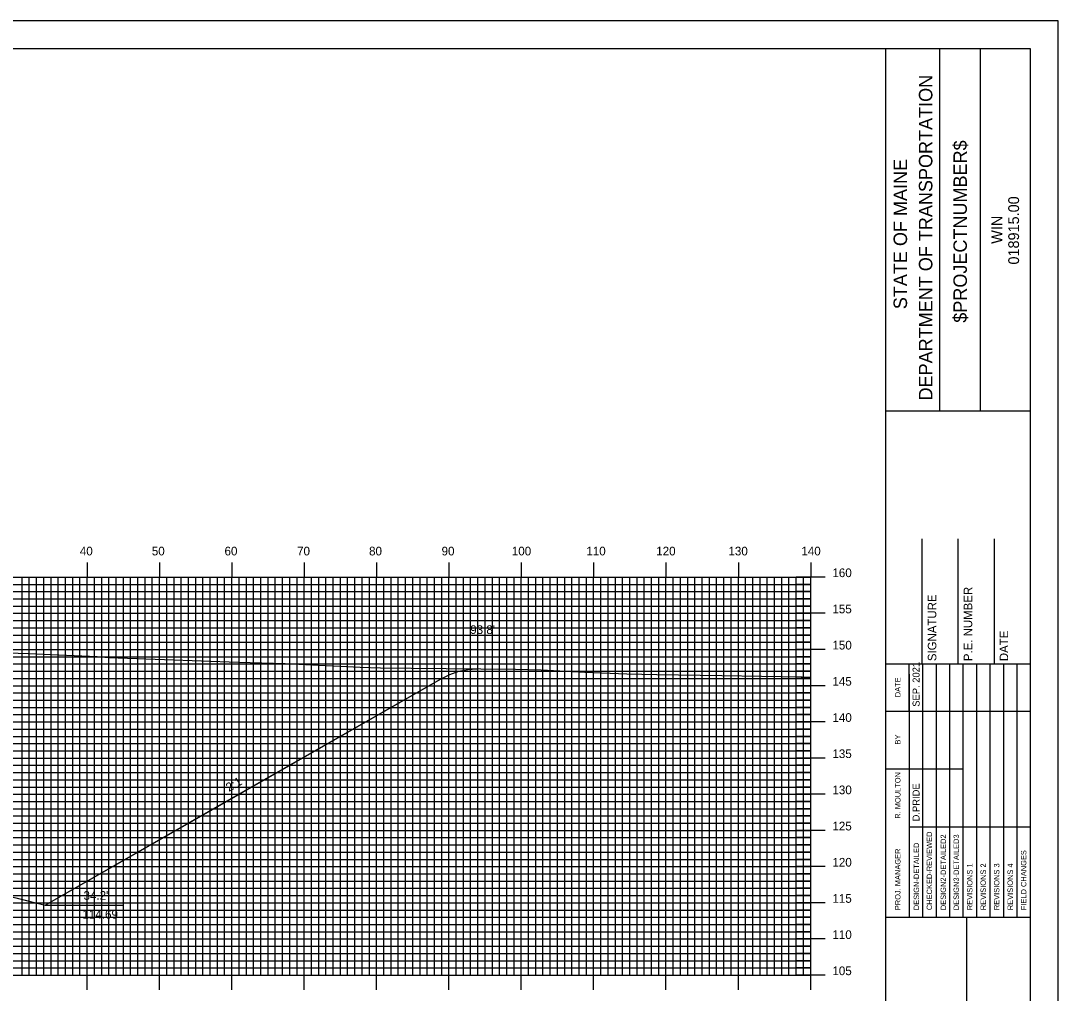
# Model space of a CAD drawing. Extents: x 1769661 to 1770005, y 442591 to 442811.
# Drawn here: x 1769857.8 to 1770001.2, y 442676.2 to 442810.5 of the extents above; entities that cross this region are included whole.
import ezdxf

# ---------------------------------------------------------------- set-up
doc = ezdxf.new("R2010")
doc.units = 0
for name, color, linetype in [('ANNOTATION', 7, 'Continuous'), ('BORDER', 7, 'Continuous'), ('D_Roadway_Centerline', 7, 'Continuous'), ('D_Roadway_SlopeLines', 7, 'Continuous'), ('D_Text_Standard', 7, 'Continuous'), ('H_V ANNOTATION', 7, 'Continuous'), ('MAJOR', 7, 'Continuous'), ('MINOR', 7, 'Continuous'), ('PDRAIN', 7, 'Continuous'), ('PLOT BOUNDARY', 7, 'Continuous'), ('S_Roadway_Centerline', 7, 'Continuous')]:
    doc.layers.add(name, color=color, linetype=linetype)

msp = doc.modelspace()

# ---------------------------------------------------------------- linework, layer by layer
at = {"layer": 'BORDER'}
for p, q in [((1769977.41, 442596.67), (1769977.41, 442806.67)), ((1769984.87, 442756.66), (1769984.87, 442806.66)), ((1769990.46, 442756.66), (1769990.46, 442806.66)), ((1769977.42, 442756.65), (1769997.41, 442756.65)), ((1769982.41, 442721.67), (1769982.41, 442738.97)), ((1769987.41, 442721.67), (1769987.41, 442738.97)), ((1769992.41, 442721.67), (1769992.41, 442738.97)), ((1769977.41, 442721.67), (1769997.41, 442721.67)), ((1769977.41, 442686.67), (1769997.41, 442686.67)), ((1769988.6, 442616.67), (1769988.6, 442686.67))]:
    msp.add_line(p, q, dxfattribs=at)
msp.add_lwpolyline([(1769677.41, 442596.67), (1769997.41, 442596.67), (1769997.41, 442806.67), (1769677.41, 442806.67)], close=True, dxfattribs=at)
for points in [[(1769980.64, 442715.17), (1769980.64, 442721.67)], [(1769982.51, 442686.68), (1769982.51, 442721.67)], [(1769984.37, 442721.67), (1769984.37, 442686.68)], [(1769986.24, 442686.68), (1769986.24, 442721.67)], [(1769988.1, 442686.68), (1769988.1, 442721.67)], [(1769989.96, 442686.68), (1769989.96, 442721.67)], [(1769991.83, 442686.68), (1769991.83, 442721.67)], [(1769993.69, 442686.68), (1769993.69, 442721.67)], [(1769995.55, 442686.68), (1769995.55, 442721.67)], [(1769980.65, 442686.68), (1769980.65, 442720.26)], [(1769977.41, 442715.17), (1769997.41, 442715.17)], [(1769977.41, 442707.17), (1769980.65, 442707.17)], [(1769980.64, 442707.17), (1769988.1, 442707.17)], [(1769980.64, 442699.17), (1769997.41, 442699.17)]]:
    msp.add_lwpolyline(points, dxfattribs=at)
at = {"layer": 'D_Roadway_Centerline'}
msp.add_lwpolyline([(1769857.19, 442689.35), (1769861.19, 442688.35), (1769861.19, 442688.36), (1769886.93, 442703.06), (1769915.86, 442719.59), (1769916.66, 442719.99), (1769917.11, 442720.22), (1769918.36, 442720.66), (1769919.15, 442720.82), (1769919.61, 442720.92), (1769920.05, 442720.94), (1769920.86, 442720.99)], dxfattribs=at)
at = {"layer": 'D_Roadway_SlopeLines'}
for points in [[(1769861.19, 442688.35), (1769915.86, 442719.59), (1769917.11, 442720.22), (1769918.36, 442720.66), (1769919.61, 442720.92), (1769920.86, 442720.99)], [(1769847.02, 442691.9), (1769861.19, 442688.35)]]:
    msp.add_lwpolyline(points, dxfattribs=at)
at = {"layer": 'MAJOR'}
for p, q in [((1769867.01, 442735.67), (1769867.01, 442733.67)), ((1769877.01, 442735.67), (1769877.01, 442733.67)), ((1769887.01, 442735.67), (1769887.01, 442733.67)), ((1769897.01, 442735.67), (1769897.01, 442733.67)), ((1769907.01, 442735.67), (1769907.01, 442733.67)), ((1769917.01, 442735.67), (1769917.01, 442733.67)), ((1769927.01, 442735.67), (1769927.01, 442733.67)), ((1769937.01, 442735.67), (1769937.01, 442733.67)), ((1769947.01, 442735.67), (1769947.01, 442733.67)), ((1769957.01, 442735.67), (1769957.01, 442733.67)), ((1769967.01, 442735.67), (1769967.01, 442733.67)), ((1769687.01, 442733.67), (1769967.01, 442733.67)), ((1769687.01, 442733.67), (1769967.01, 442733.67)), ((1769867.01, 442678.67), (1769867.01, 442733.67)), ((1769877.01, 442678.67), (1769877.01, 442733.67)), ((1769887.01, 442678.67), (1769887.01, 442733.67)), ((1769897.01, 442678.67), (1769897.01, 442733.67)), ((1769907.01, 442678.67), (1769907.01, 442733.67)), ((1769917.01, 442678.67), (1769917.01, 442733.67)), ((1769927.01, 442678.67), (1769927.01, 442733.67)), ((1769937.01, 442678.67), (1769937.01, 442733.67)), ((1769947.01, 442678.67), (1769947.01, 442733.67)), ((1769957.01, 442678.67), (1769957.01, 442733.67)), ((1769969.02, 442733.67), (1769965.01, 442733.67)), ((1769967.01, 442678.67), (1769967.01, 442733.67)), ((1769967.01, 442678.67), (1769967.01, 442733.67)), ((1769687.01, 442728.67), (1769967.01, 442728.67)), ((1769969.02, 442728.67), (1769965.01, 442728.67)), ((1769687.01, 442723.67), (1769967.01, 442723.67)), ((1769969.02, 442723.67), (1769965.01, 442723.67)), ((1769687.01, 442718.67), (1769967.01, 442718.67)), ((1769969.02, 442718.67), (1769965.01, 442718.67)), ((1769687.01, 442713.67), (1769967.01, 442713.67)), ((1769969.02, 442713.67), (1769965.01, 442713.67)), ((1769687.01, 442708.67), (1769967.01, 442708.67)), ((1769969.02, 442708.67), (1769965.01, 442708.67)), ((1769687.01, 442703.67), (1769967.01, 442703.67)), ((1769969.02, 442703.67), (1769965.01, 442703.67)), ((1769687.01, 442698.67), (1769967.01, 442698.67)), ((1769969.02, 442698.67), (1769965.01, 442698.67)), ((1769687.01, 442693.67), (1769967.01, 442693.67)), ((1769969.02, 442693.67), (1769965.01, 442693.67)), ((1769687.01, 442688.67), (1769967.01, 442688.67)), ((1769969.02, 442688.67), (1769965.01, 442688.67)), ((1769687.01, 442683.67), (1769967.01, 442683.67)), ((1769969.02, 442683.67), (1769965.01, 442683.67)), ((1769687.01, 442678.67), (1769967.01, 442678.67)), ((1769687.01, 442678.67), (1769967.01, 442678.67)), ((1769867.01, 442676.66), (1769867.01, 442678.67)), ((1769877.01, 442676.66), (1769877.01, 442678.67)), ((1769887.01, 442676.66), (1769887.01, 442678.67)), ((1769897.01, 442676.66), (1769897.01, 442678.67)), ((1769907.01, 442676.66), (1769907.01, 442678.67)), ((1769917.01, 442676.66), (1769917.01, 442678.67)), ((1769927.01, 442676.66), (1769927.01, 442678.67)), ((1769937.01, 442676.66), (1769937.01, 442678.67)), ((1769947.01, 442676.66), (1769947.01, 442678.67)), ((1769957.01, 442676.66), (1769957.01, 442678.67)), ((1769969.02, 442678.67), (1769965.01, 442678.67)), ((1769967.01, 442676.66), (1769967.01, 442678.67))]:
    msp.add_line(p, q, dxfattribs=at)
at = {"layer": 'MINOR'}
for p, q in [((1769687.01, 442732.67), (1769967.01, 442732.67)), ((1769858.01, 442678.67), (1769858.01, 442733.67)), ((1769859.01, 442678.67), (1769859.01, 442733.67)), ((1769860.01, 442678.67), (1769860.01, 442733.67)), ((1769861.01, 442678.67), (1769861.01, 442733.67)), ((1769862.01, 442678.67), (1769862.01, 442733.67)), ((1769863.01, 442678.67), (1769863.01, 442733.67)), ((1769864.01, 442678.67), (1769864.01, 442733.67)), ((1769865.01, 442678.67), (1769865.01, 442733.67)), ((1769866.01, 442678.67), (1769866.01, 442733.67)), ((1769868.01, 442678.67), (1769868.01, 442733.67)), ((1769869.01, 442678.67), (1769869.01, 442733.67)), ((1769870.01, 442678.67), (1769870.01, 442733.67)), ((1769871.01, 442678.67), (1769871.01, 442733.67)), ((1769872.01, 442678.67), (1769872.01, 442733.67)), ((1769873.01, 442678.67), (1769873.01, 442733.67)), ((1769874.01, 442678.67), (1769874.01, 442733.67)), ((1769875.01, 442678.67), (1769875.01, 442733.67)), ((1769876.01, 442678.67), (1769876.01, 442733.67)), ((1769878.01, 442678.67), (1769878.01, 442733.67)), ((1769879.01, 442678.67), (1769879.01, 442733.67)), ((1769880.01, 442678.67), (1769880.01, 442733.67)), ((1769881.01, 442678.67), (1769881.01, 442733.67)), ((1769882.01, 442678.67), (1769882.01, 442733.67)), ((1769883.01, 442678.67), (1769883.01, 442733.67)), ((1769884.01, 442678.67), (1769884.01, 442733.67)), ((1769885.01, 442678.67), (1769885.01, 442733.67)), ((1769886.01, 442678.67), (1769886.01, 442733.67)), ((1769888.01, 442678.67), (1769888.01, 442733.67)), ((1769889.01, 442678.67), (1769889.01, 442733.67)), ((1769890.01, 442678.67), (1769890.01, 442733.67)), ((1769891.01, 442678.67), (1769891.01, 442733.67)), ((1769892.01, 442678.67), (1769892.01, 442733.67)), ((1769893.01, 442678.67), (1769893.01, 442733.67)), ((1769894.01, 442678.67), (1769894.01, 442733.67)), ((1769895.01, 442678.67), (1769895.01, 442733.67)), ((1769896.01, 442678.67), (1769896.01, 442733.67)), ((1769898.01, 442678.67), (1769898.01, 442733.67)), ((1769899.01, 442678.67), (1769899.01, 442733.67)), ((1769900.01, 442678.67), (1769900.01, 442733.67)), ((1769901.01, 442678.67), (1769901.01, 442733.67)), ((1769902.01, 442678.67), (1769902.01, 442733.67)), ((1769903.01, 442678.67), (1769903.01, 442733.67)), ((1769904.01, 442678.67), (1769904.01, 442733.67)), ((1769905.01, 442678.67), (1769905.01, 442733.67)), ((1769906.01, 442678.67), (1769906.01, 442733.67)), ((1769908.01, 442678.67), (1769908.01, 442733.67)), ((1769909.01, 442678.67), (1769909.01, 442733.67)), ((1769910.01, 442678.67), (1769910.01, 442733.67)), ((1769911.01, 442678.67), (1769911.01, 442733.67)), ((1769912.01, 442678.67), (1769912.01, 442733.67)), ((1769913.01, 442678.67), (1769913.01, 442733.67)), ((1769914.01, 442678.67), (1769914.01, 442733.67)), ((1769915.01, 442678.67), (1769915.01, 442733.67)), ((1769916.01, 442678.67), (1769916.01, 442733.67)), ((1769918.01, 442678.67), (1769918.01, 442733.67)), ((1769919.01, 442678.67), (1769919.01, 442733.67)), ((1769920.01, 442678.67), (1769920.01, 442733.67)), ((1769921.01, 442678.67), (1769921.01, 442733.67)), ((1769922.01, 442678.67), (1769922.01, 442733.67)), ((1769923.01, 442678.67), (1769923.01, 442733.67)), ((1769924.01, 442678.67), (1769924.01, 442733.67)), ((1769925.01, 442678.67), (1769925.01, 442733.67)), ((1769926.01, 442678.67), (1769926.01, 442733.67)), ((1769928.01, 442678.67), (1769928.01, 442733.67)), ((1769929.01, 442678.67), (1769929.01, 442733.67)), ((1769930.01, 442678.67), (1769930.01, 442733.67)), ((1769931.01, 442678.67), (1769931.01, 442733.67)), ((1769932.01, 442678.67), (1769932.01, 442733.67)), ((1769933.01, 442678.67), (1769933.01, 442733.67)), ((1769934.01, 442678.67), (1769934.01, 442733.67)), ((1769935.01, 442678.67), (1769935.01, 442733.67)), ((1769936.01, 442678.67), (1769936.01, 442733.67)), ((1769938.01, 442678.67), (1769938.01, 442733.67)), ((1769939.01, 442678.67), (1769939.01, 442733.67)), ((1769940.01, 442678.67), (1769940.01, 442733.67)), ((1769941.01, 442678.67), (1769941.01, 442733.67)), ((1769942.01, 442678.67), (1769942.01, 442733.67)), ((1769943.01, 442678.67), (1769943.01, 442733.67)), ((1769944.01, 442678.67), (1769944.01, 442733.67)), ((1769945.01, 442678.67), (1769945.01, 442733.67)), ((1769946.01, 442678.67), (1769946.01, 442733.67)), ((1769948.01, 442678.67), (1769948.01, 442733.67)), ((1769949.01, 442678.67), (1769949.01, 442733.67)), ((1769950.01, 442678.67), (1769950.01, 442733.67)), ((1769951.01, 442678.67), (1769951.01, 442733.67)), ((1769952.01, 442678.67), (1769952.01, 442733.67)), ((1769953.01, 442678.67), (1769953.01, 442733.67)), ((1769954.01, 442678.67), (1769954.01, 442733.67)), ((1769955.01, 442678.67), (1769955.01, 442733.67)), ((1769956.01, 442678.67), (1769956.01, 442733.67)), ((1769958.01, 442678.67), (1769958.01, 442733.67)), ((1769959.01, 442678.67), (1769959.01, 442733.67)), ((1769960.01, 442678.67), (1769960.01, 442733.67)), ((1769961.01, 442678.67), (1769961.01, 442733.67)), ((1769962.01, 442678.67), (1769962.01, 442733.67)), ((1769963.01, 442678.67), (1769963.01, 442733.67)), ((1769964.01, 442678.67), (1769964.01, 442733.67)), ((1769965.01, 442678.67), (1769965.01, 442733.67)), ((1769967.01, 442732.67), (1769965.01, 442732.67)), ((1769966.01, 442678.67), (1769966.01, 442733.67)), ((1769687.01, 442731.67), (1769967.01, 442731.67)), ((1769967.01, 442731.67), (1769965.01, 442731.67)), ((1769687.01, 442730.67), (1769967.01, 442730.67)), ((1769967.01, 442730.67), (1769965.01, 442730.67)), ((1769687.01, 442729.67), (1769967.01, 442729.67)), ((1769967.01, 442729.67), (1769965.01, 442729.67)), ((1769687.01, 442727.67), (1769967.01, 442727.67)), ((1769967.01, 442727.67), (1769965.01, 442727.67)), ((1769687.01, 442726.67), (1769967.01, 442726.67)), ((1769687.01, 442725.67), (1769967.01, 442725.67)), ((1769967.01, 442726.67), (1769965.01, 442726.67)), ((1769967.01, 442725.67), (1769965.01, 442725.67)), ((1769687.01, 442724.67), (1769967.01, 442724.67)), ((1769967.01, 442724.67), (1769965.01, 442724.67)), ((1769687.01, 442722.67), (1769967.01, 442722.67)), ((1769967.01, 442722.67), (1769965.01, 442722.67)), ((1769687.01, 442721.67), (1769967.01, 442721.67)), ((1769967.01, 442721.67), (1769965.01, 442721.67)), ((1769687.01, 442720.67), (1769967.01, 442720.67)), ((1769687.01, 442719.67), (1769967.01, 442719.67)), ((1769967.01, 442720.67), (1769965.01, 442720.67)), ((1769967.01, 442719.67), (1769965.01, 442719.67)), ((1769687.01, 442717.67), (1769967.01, 442717.67)), ((1769967.01, 442717.67), (1769965.01, 442717.67)), ((1769687.01, 442716.67), (1769967.01, 442716.67)), ((1769687.01, 442715.67), (1769967.01, 442715.67)), ((1769967.01, 442716.67), (1769965.01, 442716.67)), ((1769967.01, 442715.67), (1769965.01, 442715.67)), ((1769687.01, 442714.67), (1769967.01, 442714.67)), ((1769967.01, 442714.67), (1769965.01, 442714.67)), ((1769687.01, 442712.67), (1769967.01, 442712.67)), ((1769967.01, 442712.67), (1769965.01, 442712.67)), ((1769687.01, 442711.67), (1769967.01, 442711.67)), ((1769967.01, 442711.67), (1769965.01, 442711.67)), ((1769687.01, 442710.67), (1769967.01, 442710.67)), ((1769687.01, 442709.67), (1769967.01, 442709.67)), ((1769967.01, 442710.67), (1769965.01, 442710.67)), ((1769967.01, 442709.67), (1769965.01, 442709.67)), ((1769687.01, 442707.67), (1769967.01, 442707.67)), ((1769967.01, 442707.67), (1769965.01, 442707.67)), ((1769687.01, 442706.67), (1769967.01, 442706.67)), ((1769687.01, 442705.67), (1769967.01, 442705.67)), ((1769967.01, 442706.67), (1769965.01, 442706.67)), ((1769967.01, 442705.67), (1769965.01, 442705.67)), ((1769687.01, 442704.67), (1769967.01, 442704.67)), ((1769967.01, 442704.67), (1769965.01, 442704.67)), ((1769687.01, 442702.67), (1769967.01, 442702.67)), ((1769967.01, 442702.67), (1769965.01, 442702.67)), ((1769687.01, 442701.67), (1769967.01, 442701.67)), ((1769967.01, 442701.67), (1769965.01, 442701.67)), ((1769687.01, 442700.67), (1769967.01, 442700.67)), ((1769687.01, 442699.67), (1769967.01, 442699.67)), ((1769967.01, 442700.67), (1769965.01, 442700.67)), ((1769967.01, 442699.67), (1769965.01, 442699.67)), ((1769687.01, 442697.67), (1769967.01, 442697.67)), ((1769967.01, 442697.67), (1769965.01, 442697.67)), ((1769687.01, 442696.67), (1769967.01, 442696.67)), ((1769687.01, 442695.67), (1769967.01, 442695.67)), ((1769967.01, 442696.67), (1769965.01, 442696.67)), ((1769967.01, 442695.67), (1769965.01, 442695.67)), ((1769687.01, 442694.67), (1769967.01, 442694.67)), ((1769967.01, 442694.67), (1769965.01, 442694.67)), ((1769687.01, 442692.67), (1769967.01, 442692.67)), ((1769967.01, 442692.67), (1769965.01, 442692.67)), ((1769687.01, 442691.67), (1769967.01, 442691.67)), ((1769967.01, 442691.67), (1769965.01, 442691.67)), ((1769687.01, 442690.67), (1769967.01, 442690.67)), ((1769687.01, 442689.67), (1769967.01, 442689.67)), ((1769967.01, 442690.67), (1769965.01, 442690.67)), ((1769967.01, 442689.67), (1769965.01, 442689.67)), ((1769687.01, 442687.67), (1769967.01, 442687.67)), ((1769967.01, 442687.67), (1769965.01, 442687.67)), ((1769687.01, 442686.67), (1769967.01, 442686.67)), ((1769687.01, 442685.67), (1769967.01, 442685.67)), ((1769967.01, 442686.67), (1769965.01, 442686.67)), ((1769967.01, 442685.67), (1769965.01, 442685.67)), ((1769687.01, 442684.67), (1769967.01, 442684.67)), ((1769967.01, 442684.67), (1769965.01, 442684.67)), ((1769687.01, 442682.67), (1769967.01, 442682.67)), ((1769967.01, 442682.67), (1769965.01, 442682.67)), ((1769687.01, 442681.67), (1769967.01, 442681.67)), ((1769967.01, 442681.67), (1769965.01, 442681.67)), ((1769687.01, 442680.67), (1769967.01, 442680.67)), ((1769687.01, 442679.67), (1769967.01, 442679.67)), ((1769967.01, 442680.67), (1769965.01, 442680.67)), ((1769967.01, 442679.67), (1769965.01, 442679.67))]:
    msp.add_line(p, q, dxfattribs=at)
at = {"layer": 'PDRAIN'}
msp.add_line((1769861.19, 442688.35), (1769871.96, 442688.35), dxfattribs=at)
at = {"layer": 'PLOT BOUNDARY'}
msp.add_lwpolyline([(1769661.23, 442590.55), (1770001.23, 442590.55), (1770001.23, 442810.55), (1769661.23, 442810.55)], close=True, dxfattribs=at)
at = {"layer": 'S_Roadway_Centerline'}
msp.add_lwpolyline([(1769849.28, 442723.43), (1769858.83, 442723.13), (1769868.41, 442722.69), (1769869.98, 442722.57), (1769872.56, 442722.47), (1769887.9, 442721.9), (1769894.39, 442721.75), (1769904.76, 442721.23), (1769907.56, 442721.13), (1769911.82, 442721.09), (1769926.21, 442720.93), (1769929.77, 442720.85), (1769935.78, 442720.55), (1769941.59, 442720.3), (1769945.74, 442720.22), (1769954.72, 442720.07), (1769965.68, 442719.88), (1769965.83, 442719.88), (1769967.01, 442719.86)], dxfattribs=at)

# ---------------------------------------------------------------- texts
at = {"layer": 'ANNOTATION'}
msp.add_text('2:1', height=1.2, rotation=29.7451, dxfattribs=at).set_placement((1769886.6, 442703.98))
for s, p in [("34.2'", (1769866.5, 442689.08)), ('114.69', (1769866.35, 442686.48))]:
    msp.add_text(s, height=1.2, dxfattribs=at).set_placement(p)
at = {"layer": 'BORDER'}
for s, height, p in [('DEPARTMENT OF TRANSPORTATION', 1.8635, (1769983.83, 442758.08)), ('$PROJECTNUMBER$', 1.8635, (1769988.6, 442768.82)), ('STATE OF MAINE', 1.8635, (1769980.33, 442770.69)), ('018915.00', 1.491, (1769995.81, 442776.86)), ('WIN', 1.491, (1769993.49, 442779.73)), ('SIGNATURE', 1.181, (1769984.38, 442722.06)), ('P.E. NUMBER', 1.1811, (1769989.34, 442722.06)), ('DATE', 1.181, (1769994.3, 442722.06)), ('SEP. 2021', 0.969, (1769982.06, 442715.76)), ('DATE', 0.743, (1769979.42, 442717.08)), ('BY', 0.743, (1769979.42, 442710.54)), ('R. MOULTON', 0.745, (1769979.42, 442700.28)), ('D.PRIDE', 0.969, (1769982.06, 442699.92)), ('CHECKED-REVIEWED', 0.7455, (1769983.78, 442687.65)), ('DESIGN2-DETAILED2', 0.7455, (1769985.71, 442687.65)), ('DESIGN3-DETAILED3', 0.7455, (1769987.5, 442687.65)), ('PROJ. MANAGER', 0.7455, (1769979.42, 442687.65)), ('DESIGN-DETAILED', 0.7455, (1769981.99, 442687.65)), ('FIELD CHANGES', 0.7455, (1769996.82, 442687.65)), ('REVISIONS 1', 0.7455, (1769989.37, 442687.65)), ('REVISIONS 2', 0.7455, (1769991.23, 442687.65)), ('REVISIONS 3', 0.7455, (1769993.09, 442687.65)), ('REVISIONS 4', 0.7455, (1769994.96, 442687.65))]:
    msp.add_text(s, height=height, rotation=90, dxfattribs=at).set_placement(p)
at = {"layer": 'D_Text_Standard'}
msp.add_text("93.8'", height=1.2, dxfattribs=at).set_placement((1769919.95, 442725.81))
at = {"layer": 'H_V ANNOTATION'}
for s, p in [('40', (1769865.99, 442736.67)), ('50', (1769875.94, 442736.67)), ('60', (1769885.99, 442736.67)), ('70', (1769896.02, 442736.67)), ('80', (1769905.97, 442736.67)), ('90', (1769915.99, 442736.67)), ('100', (1769925.7, 442736.67)), ('110', (1769936, 442736.67)), ('120', (1769945.66, 442736.67)), ('130', (1769955.64, 442736.67)), ('140', (1769965.72, 442736.67)), ('160', (1769970.01, 442733.67)), ('155', (1769970.01, 442728.67)), ('150', (1769970.01, 442723.67)), ('145', (1769970.01, 442718.67)), ('140', (1769970.01, 442713.67)), ('135', (1769970.01, 442708.67)), ('130', (1769970.01, 442703.67)), ('125', (1769970.01, 442698.67)), ('120', (1769970.01, 442693.67)), ('115', (1769970.01, 442688.67)), ('110', (1769970.01, 442683.67)), ('105', (1769970.01, 442678.67))]:
    msp.add_text(s, height=1.2, dxfattribs=at).set_placement(p)

doc.saveas('drawing.dxf')
